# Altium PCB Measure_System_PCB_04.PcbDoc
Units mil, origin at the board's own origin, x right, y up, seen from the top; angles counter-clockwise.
Board outline 6000 x 4000 mil, 2 copper layers (Top Layer, Bottom Layer); 42 components, 34 nets, 113 pads, 0 vias.
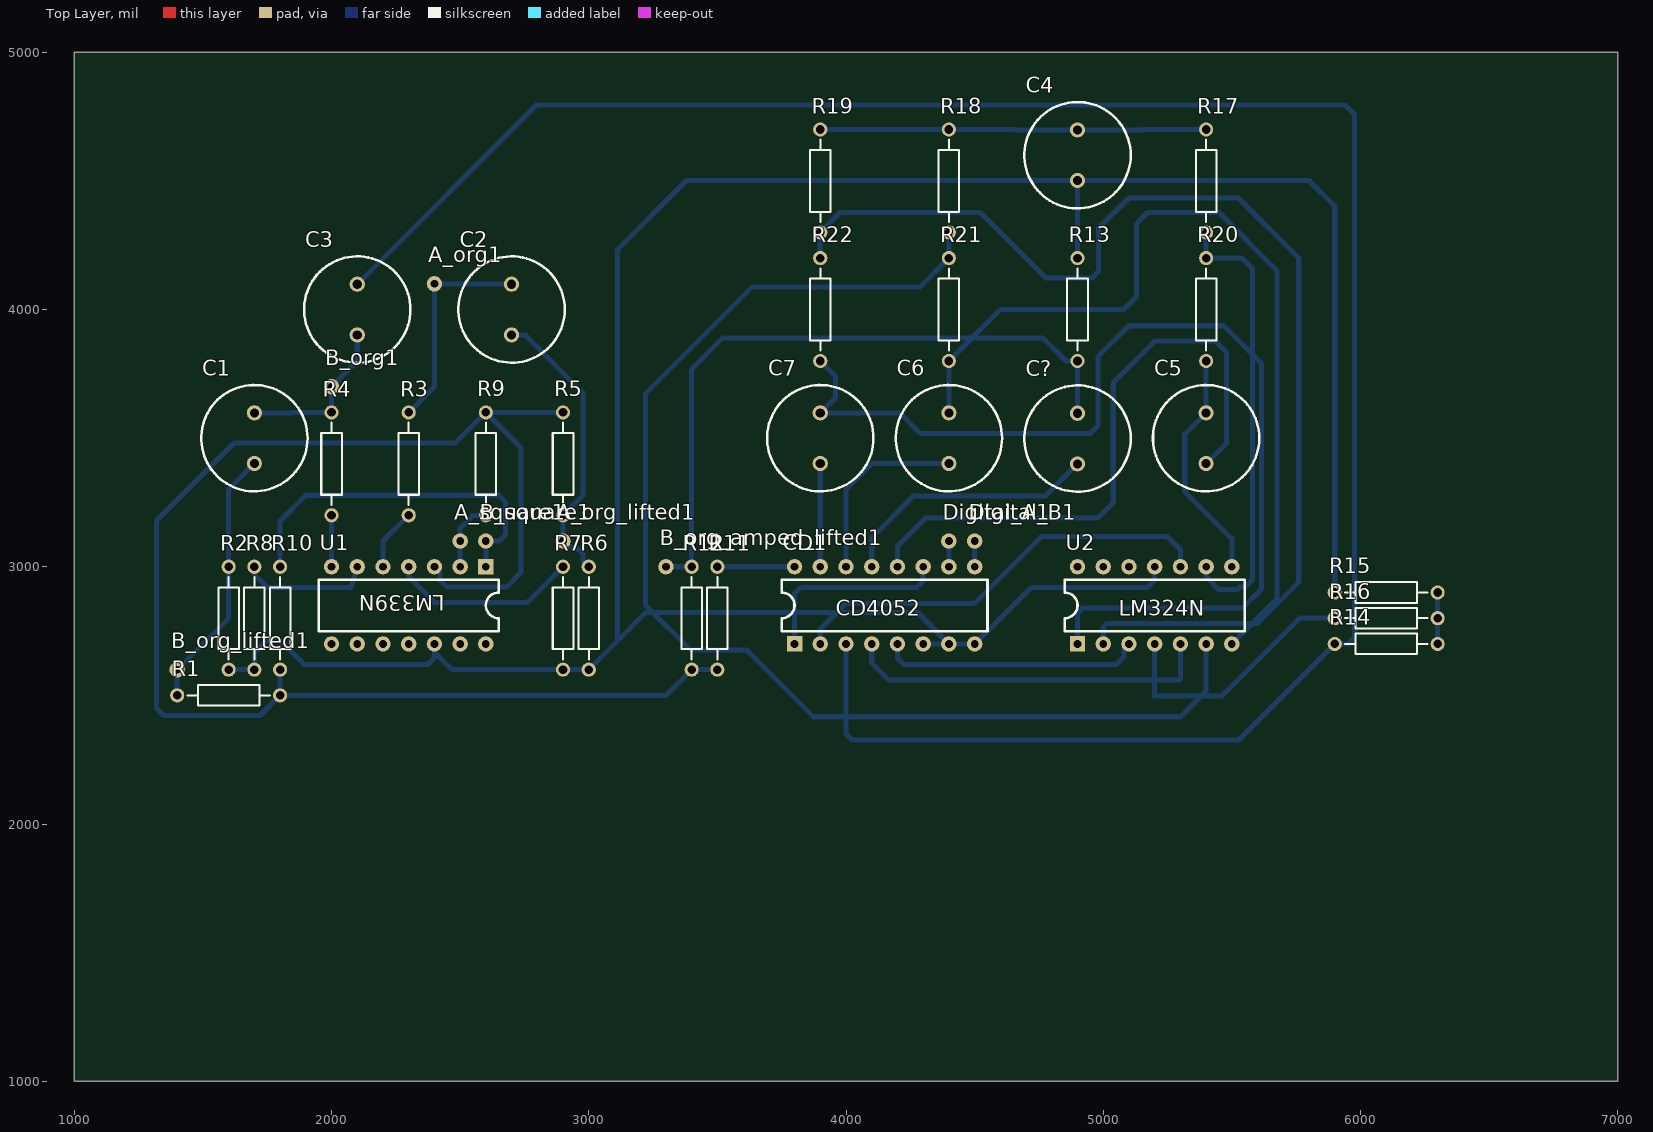
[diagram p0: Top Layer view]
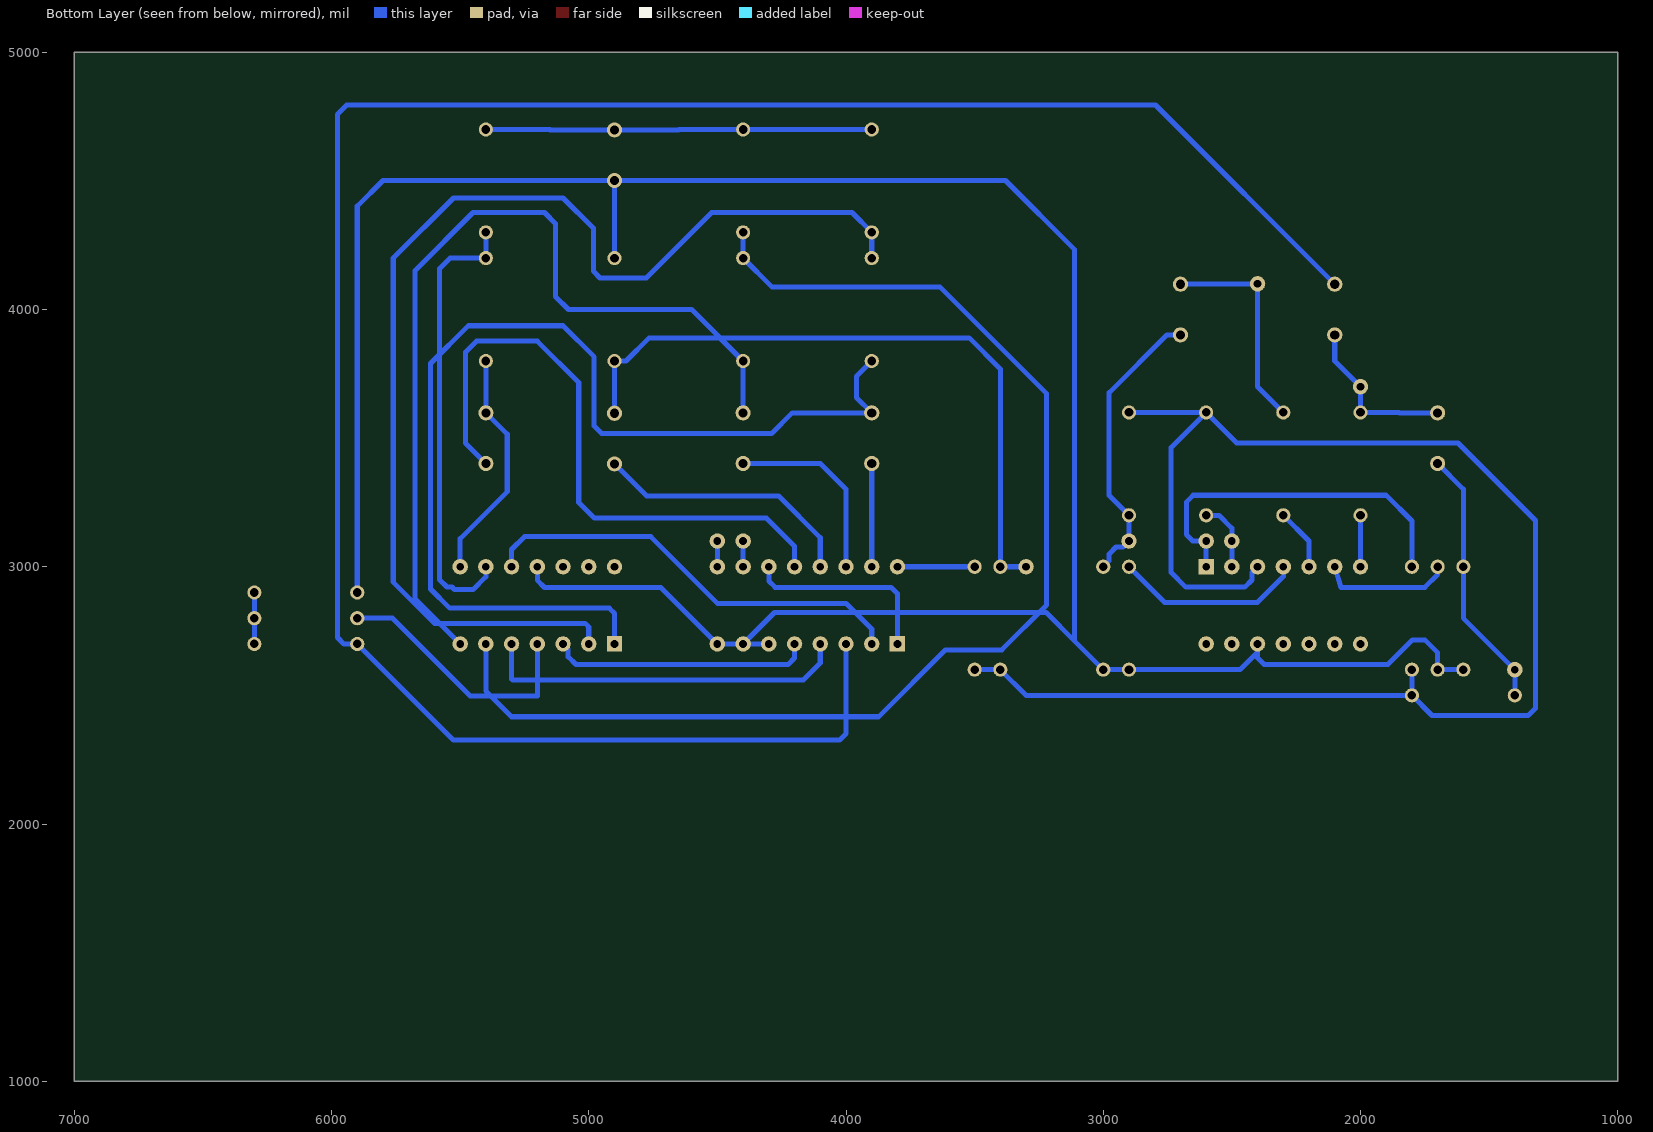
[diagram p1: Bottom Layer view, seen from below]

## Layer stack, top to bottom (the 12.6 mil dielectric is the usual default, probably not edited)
Top Solder: solder mask 0.4, Solder Resist, Dk 3.5
Top Layer: signal copper 1.4
Dielectric 1: dielectric 12.6, FR-4, Dk 4.8
Bottom Layer: signal copper 1.4
Bottom Solder: solder mask 0.4, Solder Resist, Dk 3.5

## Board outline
1000,1000 7000,1000 7000,5000 1000,5000

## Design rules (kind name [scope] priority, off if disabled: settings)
Clearance [All] p1: gap=39.37 ignorepadtopadclearanceinfootprint=FALSE
PolygonConnect [All] p1: connectstyle=Relief reliefconductorwidth=10 reliefentries=4 polygonreliefangle="90 Angle" airgapwidth=10
RoutingLayers [All] p1: top layer_v5=FALSE bottom layer_v5=TRUE
RoutingVias [All] p1: holewidth=28 width=50 viastyle="Through Hole" minholewidth=28 minwidth=50 maxholewidth=28 maxwidth=50
SolderMaskExpansion [All] p1: expansion=4 istentingtop=FALSE
Width [All] p1: maxlimit=393.7 minlimit=19.68 preferedwidth=19.68
29 further rules are at their usual default settings.

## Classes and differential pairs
component class Part_Square: C1 C2 R1 R2 R3 R4 R5 R6 R7 R8 R9 R10 U1
component class Part_PGA: C3 C4 C5 C6 C7 C? CD1 R11 R12 R13 R14 R15 R16 R17 R18 R19 R20 R21 R22 U2
component class Measure_System_Main: A_org1 A_org_lifted1 A_square1 B_org1 B_org_amped_lifted1 B_org_lifted1 B_square1 Digital_A1 Digital_B1

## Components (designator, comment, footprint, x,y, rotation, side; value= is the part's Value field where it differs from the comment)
A_org1 "Hole" Hole 2400,4100 r90 top
A_org_lifted1 "Hole" Hole 2900,3100 r90 top
A_square1 "Hole" Hole 2500,3100 r90 top
B_org1 "Hole" Hole 2000,3700 r90 top
B_org_amped_lifted1 "Hole" Hole 3300,3000 r90 top
B_org_lifted1 "Hole" Hole 1400,2600 r90 top
B_square1 "Hole" Hole 2600,3100 r90 top
C1 "Cap Pol1" RB5-10.5 1700,3500 r270 top value=10u
C2 "Cap Pol1" RB5-10.5 2700,4000 r270 top value=10u
C3 "Cap Pol1" RB5-10.5 2100,4000 r90 top value=10u
C4 "Cap Pol1" RB5-10.5 4900,4600 r90 top value=10u
C5 "Cap Pol1" RB5-10.5 5400,3500 r270 top value=10u
C6 "Cap Pol1" RB5-10.5 4400,3500 r270 top value=10u
C7 "Cap Pol1" RB5-10.5 3900,3500 r270 top value=10u
C? "Cap Pol1" RB5-10.5 4900,3498.43 r90 top value=10u
CD1 "CD4052" CD4052 3800,2700 r90 top
Digital_A1 "Hole" Hole 4400,3100 r90 top
Digital_B1 "Hole" Hole 4500,3100 r90 top
R1 "Res2" AXIAL-0.4 1600,2500 r0 top value=100k
R2 "Res2" AXIAL-0.4 1600,2800 r90 top value=100k
R3 "Res2" AXIAL-0.4 2300,3400 r90 top value=1k
R4 "Res2" AXIAL-0.4 2000,3400 r90 top value=1k
R5 "Res2" AXIAL-0.4 2900,3400 r90 top value=100k
R6 "Res2" AXIAL-0.4 3000,2800 r90 top value=100k
R7 "Res2" AXIAL-0.4 2900,2800 r90 top value=10k
R8 "Res2" AXIAL-0.4 1700,2800 r270 top value=10k
R9 "Res2" AXIAL-0.4 2600,3400 r270 top value=10k
R10 "Res2" AXIAL-0.4 1800,2800 r270 top value=10k
R11 "Res2" AXIAL-0.4 3500,2800 r270 top value=200
R12 "Res2" AXIAL-0.4 3400,2800 r270 top value=100k
R13 "Res2" AXIAL-0.4 4900,4000 r270 top value=100k
R14 "Res2" AXIAL-0.4 6100,2700 r180 top value=100k
R15 "Res2" AXIAL-0.4 6100,2900 r0 top value=100k
R16 "Res2" AXIAL-0.4 6100,2800 r0 top value=100k
R17 "Res2" AXIAL-0.4 5400,4500 r270 top value=50k
R18 "Res2" AXIAL-0.4 4400,4500 r270 top value=24k
R19 "Res2" AXIAL-0.4 3900,4500 r270 top value=12k
R20 "Res2" AXIAL-0.4 5400,4000 r270 top value=100k
R21 "Res2" AXIAL-0.4 4400,4000 r270 top value=100k
R22 "Res2" AXIAL-0.4 3900,4000 r270 top value=100k
U1 "LM339N" LM339N 2600,3000 r270 top
U2 "LM324N" LM324N 4900,2700 r90 top

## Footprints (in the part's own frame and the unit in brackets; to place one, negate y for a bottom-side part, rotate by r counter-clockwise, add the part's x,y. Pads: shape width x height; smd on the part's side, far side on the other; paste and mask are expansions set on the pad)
AXIAL-0.4 [mm] "Axial Device, Thru-Hole; 2 Leads; 0.4 in Pin Spacing"
  round 1.4 hole 0.85: 1(-5.08,0) 2(5.08,0)
  silkscreen extent -4.06,-1.02 4.06,1.02
CD4052 [mil]
  rect 60x60 hole 30: 1(0,0)
  round 60 hole 30 mask+4: 2(0,-100) 3(0,-200) 4(0,-300) 5(0,-400) 6(0,-500) 7(0,-600) 8(0,-700) 9(300,-700) 10(300,-600) 11(300,-500) 12(300,-400) 13(300,-300) 14(300,-200) 15(300,-100) 16(300,0)
  silkscreen extent 50,-750 250,50
Hole [mil]
  round 60 hole 30 mask+4: 1(0,0)
LM324N [mil]
  rect 60x60 hole 30: 1(0,0)
  round 60 hole 30 mask+4: 2(0,-100) 3(0,-200) 4(0,-300) 5(0,-400) 6(0,-500) 7(0,-600) 8(300,-600) 9(300,-500) 10(300,-400) 11(300,-300) 12(300,-200) 13(300,-100) 14(300,0)
  silkscreen extent 50,-650 250,50
LM339N [mil]
  rect 60x60 hole 30: 1(0,0)
  round 60 hole 30 mask+4: 2(0,-100) 3(0,-200) 4(0,-300) 5(0,-400) 6(0,-500) 7(0,-600) 8(300,-600) 9(300,-500) 10(300,-400) 11(300,-300) 12(300,-200) 13(300,-100) 14(300,0)
  silkscreen extent 50,-650 250,50
RB5-10.5 [mm] "Capacitor (Radial); 2 Leads"
  round 1.5 hole 0.9: 1(-2.5,0) 2(2.5,0)
  silkscreen extent -5.25,-5.25 5.25,5.25

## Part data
C1 C2 C3 C4 C5 C6 C7 C?: "Polarized Capacitor (Radial)"
R1 R2 R3 R4 R5 R6 R7 R8 R9 R10 R11 R12 R13 R14 R15 R16 R17 R18 R19 R20 R21 R22: "Resistor"

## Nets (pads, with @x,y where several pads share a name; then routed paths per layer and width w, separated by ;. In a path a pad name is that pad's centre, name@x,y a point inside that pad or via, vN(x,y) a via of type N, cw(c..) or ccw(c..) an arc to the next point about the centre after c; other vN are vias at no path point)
+5: R1.2 R5.2 R9.1 R10.2 R11.2 R12.2 U1.3 | length 5938.2
  Bottom Layer w19.68: R10.2 R1.2 ; U1.3 2422,2978 2422,2948.79 2450,2920.79 2679,2920.79 2737,2978.79 2737,3463 R9.1 ; R5.2 R9.1 ; R11.2 R12.2 3300,2500 R1.2 ; R1.2 1722,2422 1348,2422 1320,2450 1320,3180 1621,3481 2481,3481 R9.1
+12: R16.1 U2.4 | length 1027.1
  Bottom Layer w19.68: U2.4 5200,2498 5461,2498 5763,2800 R16.1
B_org: B_org1.1 C1.1 C3.1 R4.2 | length 643.6
  Bottom Layer w19.68: C1.1 1849,3598.43 1850.57,3600 R4.2 B_org1.1 2100,3800 C3.1
B_org_amp_1: CD1.1 CD1.11 | length 770.7
  Bottom Layer w19.68: CD1.1 3800,2895 3825,2920 4275,2920 4300,2945 CD1.11
B_org_amp_2.5: C5.2 CD1.12 | length 2445.1
  Bottom Layer w19.68: CD1.12 4200,3080 4308.78,3188.78 4977.78,3188.78 5039,3250 5039,3716 5200,3877 5436,3877 5479,3834 5479,3480.57 C5.2
B_org_amp_5: C6.2 CD1.14 | length 743
  Bottom Layer w19.68: CD1.14 4000,3301.57 4100,3401.57 C6.2
B_org_amp_10: C7.2 CD1.15 | length 401.6
  Bottom Layer w19.68: CD1.15 C7.2
B_org_amped: C?.1 CD1.13 | length 1031.9
  Bottom Layer w19.68: CD1.13 4100,3113.06 4261.94,3275 4775,3275 C?.1
B_org_to_amp: C3.2 CD1.3 R14.2 | length 8716.1
  Bottom Layer w19.68: C3.2 2796.57,4795 5941,4795 5977,4759 5977,2725 5952,2700 R14.2 5526,2326 4025,2326 4000,2351 CD1.3
B_org_to_amp_2.5: CD1.2 U2.10 | length 1694.4
  Bottom Layer w19.68: CD1.2 3900,2758 4000,2858 4500,2858 4759,3117 5250,3117 5300,3067 U2.10
B_org_to_amp_5: CD1.4 U2.5 | length 1439
  Bottom Layer w19.68: CD1.4 4100,2626 4166,2560 5296,2560 5300,2564 U2.5
B_org_to_amp_10: CD1.5 U2.3 | length 1016.1
  Bottom Layer w19.68: CD1.5 4200,2645 4225,2620 5050,2620 5080,2650 5080,2680 U2.3
Digital_A: CD1.10 Digital_A1.1 | length 100
  Bottom Layer w19.68: CD1.10 Digital_A1.1
Digital_B: CD1.9 Digital_B1.1 | length 100
  Bottom Layer w19.68: CD1.9 Digital_B1.1
GND: C4.1 CD1.6 CD1.7 CD1.8 R2.1 R6.1 R7.1 R8.2 R13.1 R15.1 U1.12 U2.11 | length 10481.3
  Bottom Layer w19.68: R2.1 R8.2 1700,2666 1750,2716 1798,2716 1894,2620 2374,2620 2400,2646 2400,2668 ; U1.12 2400,2668 ; CD1.6 CD1.7 ; R13.1 C4.1 ; U2.11 5200,2948 5171.73,2919.73 4719.73,2919.73 CD1.8 CD1.7 ; R15.1 5900,4401.57 5800,4501.57 C4.1 ; 2400,2668 2468,2600 R7.1 R6.1 3112.34,2712.33 ; 3112.34,2712.33 3222,2822 4278,2822 CD1.7 ; 3112.34,2712.33 3112.34,4233.91 3380,4501.57 C4.1
NetA_org1_1: A_org1.1 C2.1 R3.2 | length 842.1
  Bottom Layer w19.68: R3.2 2400,3700 A_org1.1 2549,4100 2550.57,4098.43 C2.1
NetA_org_lifted1_1: A_org_lifted1.1 C2.2 R5.1 R6.2 | length 1136.2
  Bottom Layer w19.68: C2.2 2752.42,3901.58 2977,3677 2977,3277 R5.1 2900,3149 A_org_lifted1.1 2923,3077 2950,3077 2977,3050 2977,3023 R6.2
NetA_square1_1: A_square1.1 R9.2 U1.2 | length 270.7
  Bottom Layer w19.68: U1.2 A_square1.1 2500,3150 2550,3200 R9.2
NetB_org_amped_lifted1_1: B_org_amped_lifted1.1 C?.2 R12.1 R13.2 | length 2659.5
  Bottom Layer w19.68: B_org_amped_lifted1.1 R12.1 3400,3769 3521,3890 4765,3890 4855,3800 R13.2 C?.2
NetB_org_lifted1_1: B_org_lifted1.1 C1.2 R1.1 R2.2 | length 1025.8
  Bottom Layer w19.68: R1.1 B_org_lifted1.1 1600,2800 R2.2 1600,3301.58 C1.2
NetB_square1_1: B_square1.1 R10.1 U1.1 | length 1421
  Bottom Layer w19.68: R10.1 1800,3178 1900,3278 2650,3278 2677,3251 2677,3125 2652,3100 B_square1.1 U1.1
NetC4_2: C4.2 R17.1 R18.1 R19.1 | length 1501.3
  Bottom Layer w19.68: R19.1 R18.1 4650,4700 4651.57,4698.43 C4.2 5150,4698.43 5151.57,4700 R17.1
NetC5_1: C5.1 R20.2 U2.8 | length 910.2
  Bottom Layer w19.68: R20.2 C5.1 5317,3515.43 5317,3292 5500,3109 U2.8
NetC6_1: C6.1 R21.2 U2.7 | length 3499.6
  Bottom Layer w19.68: C6.1 R21.2 4600,4000 5079,4000 5129,4050 5129,4334 5172,4377 5450,4377 5675,4152 5675,2875 U2.7
NetC7_1: C7.1 R22.2 U2.1 | length 4141
  Bottom Layer w19.68: R22.2 3960,3740 3960,3658.43 C7.1 4208.57,3598.43 4289,3518 4950,3518 4979,3547 4979,3816 5100,3937 5468,3937 5615,3790 5615,2914 5540,2839 4920,2839 4900,2819 U2.1
NetCD1_16: CD1.16 R11.1 | length 300
  Bottom Layer w19.68: R11.1 CD1.16
NetR3_1: R3.1 U1.5 | length 241.4
  Bottom Layer w19.68: U1.5 2200,3100 R3.1
NetR4_1: R4.1 U1.7 | length 200
  Bottom Layer w19.68: U1.7 R4.1
NetR7_2: R7.2 U1.4 | length 737
  Bottom Layer w19.68: U1.4 2300,2961.73 2400,2861.73 2761.73,2861.73 R7.2
NetR8_1: R8.1 U1.6 | length 509.5
  Bottom Layer w19.68: R8.1 1700,2970 1750,2920 2075,2920 U1.6
NetR14_1: R14.1 R15.2 R16.2 | length 200
  Bottom Layer w19.68: R14.1 R16.2 R15.2
NetR17_2: R17.2 R20.1 U2.9 | length 1761.8
  Bottom Layer w19.68: U2.9 5400,2961 5450,2911 5522,2911 5532,2921 5551,2921 5580,2950 5580,4159 5539,4200 R20.1 R17.2
NetR18_2: R18.2 R21.1 U2.6 | length 4904.5
  Bottom Layer w19.68: R18.2 R21.1 4287,4087 3634,4087 3220,3673 3220,2851 3394,2677 3613,2677 3873,2417 5300,2417 5400,2517 U2.6
NetR19_2: R19.2 R22.1 U2.2 | length 4578.8
  Bottom Layer w19.68: R22.1 R19.2 3977,4377 4522,4377 4776,4123 4956,4123 4982,4149 4982,4316 5100,4434 5526,4434 5760,4200 5760,2940 5599.89,2779.89 5013.89,2779.89 5000,2766 U2.2
pads on no net: U1.8 U1.9 U1.10 U1.11 U1.13 U1.14 U2.12 U2.13 U2.14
